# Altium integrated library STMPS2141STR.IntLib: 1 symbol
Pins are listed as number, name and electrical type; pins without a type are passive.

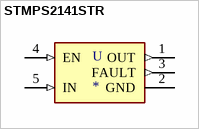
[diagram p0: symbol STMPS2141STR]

## STMPS2141STR
designator U
Power Switch/Driver 1:1 N-Channel 500mA SOT-23-5; MP: STMPS2141STR; MF: STMicroelectronics
footprint SOT95P280X145-5N
pins: 1 OUT (out), 2 GND (power), 3 FAULT (out), 4 EN (in), 5 IN (in)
